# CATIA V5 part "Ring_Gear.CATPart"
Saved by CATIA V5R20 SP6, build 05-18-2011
Part number: Ring_Gear
Source: Unknown
Bounding box of the stored display mesh (mm): x -24.5 to 24.5, y -24.49 to 24.49, z -3 to 3
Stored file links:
  E:\#01 CATIA Lecture Materials\#06 DMU\#16 DMU Page01 KIN EX16\Ring_Gear.CATPart
  C:\Program Files\Dassault Systemes\B20\win_b64\startup\materials\French\Catalog.CATMaterial
  C:\usr\gt1\projet\valve\doc\doc_2005\comp\gears\bevel_gear_files\bevel_gear.CATPart
  C:\usr\gt1\projet\valve\doc\doc_2005\regulator\sensor_block.CATProduct
  C:\usr\gt1\projet\valve\doc\doc_2005\valve4\feedback\sensor_shaft.CATPart
  C:\usr\gt1\projet\valve\doc\doc_2005\gearbox\motor_flange.CATPart
  C:\usr\gt1\projet\valve\doc\doc_2005\gearbox\positioner.CATProduct
  C:\usr\gt1\projet\valve\doc\doc_2005\gearbox\manifold.CATPart
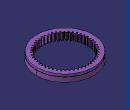
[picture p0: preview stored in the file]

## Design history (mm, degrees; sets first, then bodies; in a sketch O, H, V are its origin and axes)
Body1 (main body)
  Solid1: solid without history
